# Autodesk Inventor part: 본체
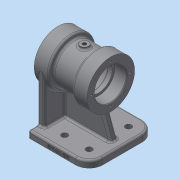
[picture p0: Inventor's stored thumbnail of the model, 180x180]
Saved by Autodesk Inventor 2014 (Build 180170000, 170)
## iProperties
Created: 2020-06
Part Number: 본체
Material: Generic
Document SubType Name: Modeling
Designer: kh
Density: 1 g/cm^3
Appearance: Default
Mass: 268.673 g
Surface Area: 641.499 cm^2
Volume: 268.673 cm^3
Author: kh
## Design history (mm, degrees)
sketch "Sketch1"
  geometry: L1 (-45, -49)-(45, -49); L2 (45, -49)-(45, 49); L3 (45, 49)-(-45, 49); L4 (-45, 49)-(-45, -49); L5 (-45, -49)-(45, 49); L6 (45, -49)-(-45, 49); 1 further point
  constraints: 12 end point, 2 midpoint, 2 parallel, 1 horizontal, 1 perpendicular
  dimensions: "d0" = 90 distance of L3.end L2.end; "d1" = 98 distance of L2.end L1.end
extrude "Extrusion1" new body sketch "Sketch1" distance "d2" = 10; taper "d3" = 0 deg
workplane "Work Plane1"
sketch "Sketch2"
  geometry: L1 (0, 49)-(151.599, 49); C1 r 35 at (80, 49)
  constraints: 2 end point, 1 centre point, 1 horizontal, 1 point on line
  dimensions: "d5" = 70 diameter of C1; "d11" = 80 distance of L1.start C1.centre
extrude "Extrusion2" join sketch "Sketch2" distance "d6" = 22; taper "d7" = 0 deg
sketch "Sketch3"
  geometry: C1 r 35 at (0, 0) reference; C2 r 29 at (0, 0); 1 further point
  constraints: 1 centre point, 1 coincident
  dimensions: "d8" = 58 diameter of C2
extrude "Extrusion3" join sketch "Sketch3" distance "d9" = 34; taper "d10" = 0 deg
sketch "Sketch4"
  geometry: C1 r 29 at (0, 0) reference; C2 r 35 at (0, 0); 1 further point
  constraints: 1 centre point, 1 coincident
  dimensions: "d12" = 70 diameter of C2
extrude "Extrusion4" join sketch "Sketch4" distance "d13" = 22; taper "d14" = 0 deg
sketch "Sketch5"
  geometry: L1 (-45, 35)-(-35, 35); L2 (-35, 35)-(-35, -35); L3 (-35, -35)-(-45, -35); L4 (-45, -35)-(-45, 35); 3 further points
  constraints: 8 end point, 2 parallel, 1 horizontal, 1 horizontal alignment, 1 midpoint, 1 perpendicular, 1 vertical alignment
  dimensions: "d15" = 70 distance of L3.end L1.start; "d16" = 10 distance of L1.start L1.end
extrude "Extrusion5" join sketch "Sketch5" stored distance "d17" = 22; taper "d18" = 0 deg
sketch "Sketch6"
  geometry: L1 (35, 10)-(35, 80) reference; L2 (45, 10)-(-45, 10) reference; L3 (-33, 10)-(-11.042, 70.329); 1 further point
  constraints: 2 end point, 1 point on line
  dimensions: "d19" = 70 deg angle of L2 L3; "d20" = 12 distance of L2.end L3.start
feature "Rib1" sketch "Sketch6" dims "d21" = 1, "d22" = 10, "d23" = 0, "d24" = 0, "d25" = 1, "d26" = 1
sketch "Sketch7"
  geometry: L1 (-28, 115)-(-28, 45) reference; L2 (50, 115)-(50, 45) reference; L3 (-28, 80)-(50, 80); L4 (-28, 103.5)-(-10, 103.5); L5 (-10, 103.5)-(-10, 102.461); L6 (-10, 102.461)-(-10, 100); L7 (-10, 100)-(-4, 100); L8 (-4, 100)-(-4, 103); L9 (-4, 103)-(26, 103); L10 (26, 103)-(26, 100); L11 (26, 100)-(32, 100); L12 (32, 100)-(32, 103.5); L13 (32, 103.5)-(50, 103.5); L14 (-28, 103.5)-(-28, 80); L15 (50, 103.5)-(50, 80); 1 further point
  constraints: 26 end point, 4 parallel, 4 perpendicular, 3 collinear, 2 midpoint, 2 point on line, 1 horizontal alignment
  dimensions: "d27" = 47 diameter of L4 L3; "d28" = 40 diameter of L7 L3; "d29" = 46 diameter of L9 L3; "d30" = 40 diameter of L11 L3; "d31" = 47 diameter of L13 L3; "d32" = 18 distance of L4.start L4.end; "d33" = 18 distance of L12.end L13.end; "d34" = 30 distance of L8.end L9.end; "d35" = 6 distance of L6.end L7.end
revolve "Revolution1" sketch "Sketch7" stored, may be unused: angle "d36" = 90 deg
workplane "Work Plane3"
sketch "Sketch9"
  geometry: L1 (-56, 35)-(-56, -35) reference; C1 r 6 at (-17, 0); 1 further point
  constraints: 1 centre point, 1 horizontal alignment, 1 midpoint
  dimensions: "d39" = 12 diameter of C1; "d40" = 39 distance of point (-56, 0) C1.centre
extrude "Extrusion6" join sketch "Sketch9" stored distance "d41" = 22; taper "d42" = 0 deg
hole "Hole1" diameter "d45" = 5.188; stored, may be unused: countersink angle "d49" = 90 deg, drill point angle "d51" = 118 deg; dims "d43" = 10, "d44" = 10, "d46" = 6, "d47" = 4, "d48" = 2, "d50" = 8
sketch "Sketch10"
  geometry: L1 (0, 0)-(-42.314, 0); C1 r 23.5 at (0, 0) reference; C2 r 35 at (0, 0) reference; 2 further points
  constraints: 2 end point, 1 horizontal, 1 point on line
  dimensions: "d52" = 28.5 distance of C1.centre point (-28.5, 0)
hole "Hole2" sketch "Sketch10" at (-28.5, 0) diameter "d53" = 3.242; stored, may be unused: countersink angle "d57" = 90 deg, drill point angle "d59" = 118 deg; dims "d54" = 10, "d55" = 4, "d56" = 2, "d58" = 12
pattern_circular "Circular Pattern1" dims angle "d61" = 360 deg
sketch "Sketch11"
  geometry: L1 (0, 0)-(44.212, 0); C1 r 23.5 at (0, 0) reference; C2 r 35 at (0, 0) reference; 2 further points
  constraints: 2 end point, 1 horizontal, 1 point on line
  dimensions: "d63" = 28.5 distance of C1.centre point (28.5, 0)
hole "Hole3" sketch "Sketch11" at (28.5, 0) diameter "d64" = 3.242; stored, may be unused: countersink angle "d68" = 90 deg, drill point angle "d70" = 118 deg; dims "d65" = 10, "d66" = 4, "d67" = 2, "d69" = 12
pattern_circular "Circular Pattern2" dims angle "d72" = 360 deg
fillet "Fillet1" dims "d74" = 20
sketch "Sketch12"
  geometry: A1 r 20 centre (25, -29) between (25, -49) and (45, -29) reference; A2 r 20 centre (25, 29) between (45, 29) and (25, 49) reference; 1 further point
hole "Hole4" sketch "Sketch12" at (25, -29), (25, 29) diameter "d75" = 9; stored, may be unused: countersink angle "d79" = 90 deg, drill point angle "d81" = 0 deg; dims "d76" = 10, "d77" = 4, "d78" = 2, "d80" = 12
pattern_linear "Rectangular Pattern1" dims "d84" = 36
fillet "Fillet2" dims "d85" = 3
chamfer "Chamfer1" distance "d86" = 1; stored, may be unused: second distance "d87" = 2, angle "d88" = 45 deg
fillet "Fillet3" dims "d89" = 0.3, "d90" = 3
fillet "Fillet4" dims "d91" = 3
fillet "Fillet5" dims "d92" = 3
fillet "Fillet6" dims "d93" = 3
fillet "Fillet7" dims "d94" = 3
fillet "Fillet8" dims "d95" = 3
fillet "Fillet9" dims "d96" = 3
sketch "Sketch14"
  geometry: L1 (0, 0)-(67, 0) reference; L2 (-3, 7)-(-3, 0) reference; 2 further points
  constraints: 1 other
  dimensions: "d97" = 4 distance from line of L1 point (42, 4); "d98" = 45 distance from line of L2 point (42, 4)
emboss "Emboss1" sketch "Sketch14" dims "d0" = 90, "d1" = 98, "d99" = 0.5, "d100" = 0
body "Solid1"
other parameters: "d4" = 5
